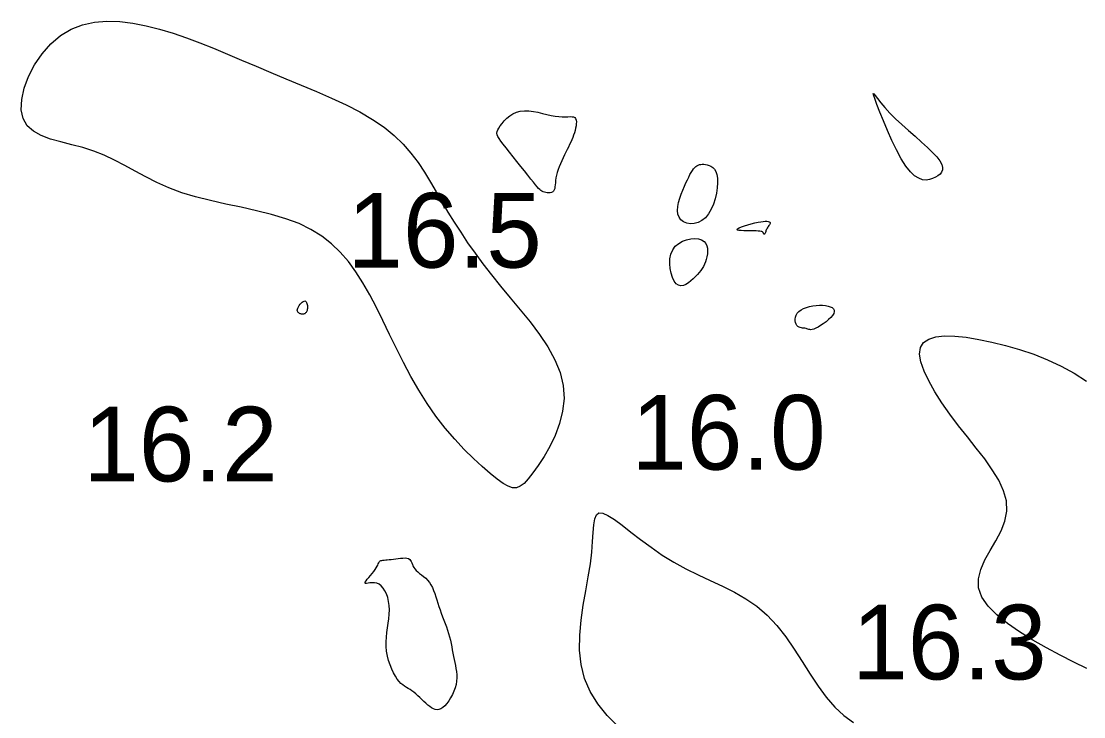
# Model space of a CAD drawing. Extents: x 3040093 to 3056816, y 408076 to 509144.
# Drawn here: x 3045442.3 to 3045513.5, y 434324.5 to 434371 of the extents above; entities that cross this region are included whole.
import ezdxf

# ---------------------------------------------------------------- set-up
doc = ezdxf.new("R2010")
doc.units = 0
doc.layers.add('V-CHAN-CONT-EL17', color=7, linetype='Continuous')
doc.layers.add('V-TOPO-SOUN-0610', color=7, linetype='Continuous')

msp = doc.modelspace()

# ---------------------------------------------------------------- linework, layer by layer
at = {"layer": 'V-CHAN-CONT-EL17'}
for points in [[(3045468.936, 434346.351), (3045468.412, 434347.27), (3045467.918, 434348.208), (3045467.446, 434349.153), (3045466.991, 434350.091), (3045466.546, 434351.012), (3045466.105, 434351.902), (3045465.661, 434352.75), (3045465.208, 434353.545), (3045464.735, 434354.283), (3045464.233, 434354.966), (3045463.691, 434355.591), (3045463.1, 434356.159), (3045462.449, 434356.667), (3045461.728, 434357.117), (3045460.928, 434357.506), (3045460.042, 434357.836), (3045459.087, 434358.119), (3045458.084, 434358.368), (3045457.054, 434358.597), (3045456.017, 434358.818), (3045454.994, 434359.046), (3045454.006, 434359.293), (3045453.074, 434359.574), (3045452.214, 434359.897), (3045451.416, 434360.254), (3045450.668, 434360.631), (3045449.956, 434361.016), (3045449.265, 434361.394), (3045448.583, 434361.753), (3045447.895, 434362.081), (3045447.187, 434362.362), (3045446.452, 434362.591), (3045445.709, 434362.785), (3045444.983, 434362.968), (3045444.296, 434363.162), (3045443.676, 434363.392), (3045443.145, 434363.682), (3045442.729, 434364.053), (3045442.453, 434364.531), (3045442.334, 434365.129), (3045442.366, 434365.822), (3045442.535, 434366.577), (3045442.828, 434367.36), (3045443.231, 434368.137), (3045443.73, 434368.874), (3045444.312, 434369.537), (3045444.964, 434370.092), (3045445.673, 434370.513), (3045446.43, 434370.804), (3045447.23, 434370.978), (3045448.063, 434371.048), (3045448.923, 434371.025), (3045449.803, 434370.922), (3045450.696, 434370.751), (3045451.594, 434370.525), (3045452.492, 434370.255), (3045453.391, 434369.947), (3045454.296, 434369.607), (3045455.211, 434369.241), (3045456.138, 434368.854), (3045457.082, 434368.451), (3045458.047, 434368.037), (3045459.036, 434367.619), (3045460.05, 434367.2), (3045461.076, 434366.778), (3045462.099, 434366.349), (3045463.104, 434365.908), (3045464.073, 434365.452), (3045464.993, 434364.978), (3045465.846, 434364.479), (3045466.618, 434363.954), (3045467.298, 434363.399), (3045467.894, 434362.817), (3045468.421, 434362.211), (3045468.892, 434361.585), (3045469.321, 434360.942), (3045469.722, 434360.287), (3045470.11, 434359.623), (3045470.496, 434358.954), (3045470.895, 434358.282), (3045471.311, 434357.606), (3045471.75, 434356.923), (3045472.213, 434356.23), (3045472.707, 434355.526), (3045473.235, 434354.807), (3045473.801, 434354.07), (3045474.409, 434353.314), (3045475.058, 434352.536), (3045475.727, 434351.738), (3045476.387, 434350.923), (3045477.012, 434350.093), (3045477.574, 434349.25), (3045478.047, 434348.398), (3045478.402, 434347.538), (3045478.614, 434346.674), (3045478.663, 434345.809), (3045478.569, 434344.956), (3045478.361, 434344.127), (3045478.065, 434343.336), (3045477.711, 434342.597), (3045477.327, 434341.923), (3045476.94, 434341.327), (3045476.58, 434340.822), (3045476.266, 434340.421), (3045475.99, 434340.123), (3045475.735, 434339.926), (3045475.484, 434339.83), (3045475.221, 434339.831), (3045474.93, 434339.929), (3045474.594, 434340.122), (3045474.195, 434340.408), (3045473.724, 434340.783), (3045473.189, 434341.244), (3045472.606, 434341.784), (3045471.99, 434342.397), (3045471.356, 434343.078), (3045470.719, 434343.819), (3045470.094, 434344.616), (3045469.495, 434345.462)], [(3045499.382, 434366.113), (3045499.36, 434366.217), (3045499.397, 434366.2), (3045499.495, 434366.08), (3045499.651, 434365.873), (3045499.865, 434365.596), (3045500.137, 434365.268), (3045500.466, 434364.906), (3045500.849, 434364.524), (3045501.27, 434364.133), (3045501.713, 434363.738), (3045502.158, 434363.347), (3045502.59, 434362.967), (3045502.989, 434362.606), (3045503.338, 434362.269), (3045503.62, 434361.965), (3045503.821, 434361.698), (3045503.945, 434361.467), (3045504, 434361.267), (3045503.994, 434361.095), (3045503.935, 434360.946), (3045503.832, 434360.818), (3045503.693, 434360.705), (3045503.526, 434360.605), (3045503.338, 434360.516), (3045503.131, 434360.45), (3045502.906, 434360.422), (3045502.664, 434360.445), (3045502.405, 434360.536), (3045502.132, 434360.707), (3045501.844, 434360.975), (3045501.542, 434361.353), (3045501.23, 434361.848), (3045500.914, 434362.433), (3045500.604, 434363.073), (3045500.309, 434363.734), (3045500.038, 434364.378), (3045499.801, 434364.973), (3045499.607, 434365.482), (3045499.464, 434365.871)], [(3045476.244, 434360.739), (3045476.014, 434361.028), (3045475.766, 434361.338), (3045475.509, 434361.66), (3045475.254, 434361.981), (3045475.009, 434362.289), (3045474.785, 434362.573), (3045474.592, 434362.822), (3045474.435, 434363.027), (3045474.317, 434363.194), (3045474.235, 434363.331), (3045474.187, 434363.449), (3045474.172, 434363.555), (3045474.187, 434363.66), (3045474.231, 434363.771), (3045474.302, 434363.898), (3045474.399, 434364.048), (3045474.52, 434364.213), (3045474.666, 434364.385), (3045474.835, 434364.555), (3045475.027, 434364.714), (3045475.241, 434364.853), (3045475.478, 434364.963), (3045475.736, 434365.035), (3045476.014, 434365.063), (3045476.307, 434365.053), (3045476.61, 434365.013), (3045476.918, 434364.954), (3045477.224, 434364.883), (3045477.523, 434364.81), (3045477.81, 434364.744), (3045478.078, 434364.694), (3045478.324, 434364.665), (3045478.547, 434364.655), (3045478.746, 434364.656), (3045478.921, 434364.662), (3045479.072, 434364.666), (3045479.2, 434364.661), (3045479.303, 434364.641), (3045479.383, 434364.599), (3045479.439, 434364.53), (3045479.474, 434364.436), (3045479.489, 434364.321), (3045479.487, 434364.19), (3045479.471, 434364.046), (3045479.442, 434363.893), (3045479.402, 434363.735), (3045479.355, 434363.577), (3045479.302, 434363.42), (3045479.243, 434363.265), (3045479.179, 434363.11), (3045479.11, 434362.954), (3045479.037, 434362.795), (3045478.958, 434362.632), (3045478.875, 434362.462), (3045478.788, 434362.286), (3045478.697, 434362.101), (3045478.604, 434361.909), (3045478.512, 434361.712), (3045478.424, 434361.514), (3045478.341, 434361.315), (3045478.268, 434361.118), (3045478.205, 434360.925), (3045478.156, 434360.739), (3045478.122, 434360.562), (3045478.1, 434360.394), (3045478.085, 434360.238), (3045478.073, 434360.095), (3045478.059, 434359.966), (3045478.04, 434359.854), (3045478.011, 434359.759), (3045477.966, 434359.682), (3045477.904, 434359.626), (3045477.827, 434359.588), (3045477.739, 434359.567), (3045477.643, 434359.559), (3045477.543, 434359.565), (3045477.443, 434359.581), (3045477.347, 434359.605), (3045477.259, 434359.636), (3045477.181, 434359.672), (3045477.108, 434359.718), (3045477.035, 434359.779), (3045476.955, 434359.86), (3045476.862, 434359.966), (3045476.751, 434360.102), (3045476.614, 434360.273), (3045476.446, 434360.485)], [(3045486.286, 434358.144), (3045486.262, 434358.383), (3045486.281, 434358.644), (3045486.334, 434358.918), (3045486.413, 434359.199), (3045486.51, 434359.478), (3045486.616, 434359.749), (3045486.723, 434360.002), (3045486.825, 434360.233), (3045486.92, 434360.44), (3045487.01, 434360.625), (3045487.095, 434360.789), (3045487.177, 434360.932), (3045487.256, 434361.056), (3045487.333, 434361.162), (3045487.409, 434361.251), (3045487.485, 434361.324), (3045487.562, 434361.381), (3045487.642, 434361.424), (3045487.726, 434361.454), (3045487.814, 434361.472), (3045487.91, 434361.478), (3045488.013, 434361.473), (3045488.125, 434361.459), (3045488.246, 434361.436), (3045488.373, 434361.398), (3045488.499, 434361.339), (3045488.619, 434361.255), (3045488.728, 434361.139), (3045488.821, 434360.985), (3045488.891, 434360.788), (3045488.933, 434360.542), (3045488.944, 434360.245), (3045488.922, 434359.907), (3045488.867, 434359.545), (3045488.782, 434359.174), (3045488.665, 434358.809), (3045488.517, 434358.465), (3045488.339, 434358.158), (3045488.132, 434357.903), (3045487.897, 434357.712), (3045487.643, 434357.583), (3045487.383, 434357.515), (3045487.126, 434357.502), (3045486.885, 434357.542), (3045486.669, 434357.63), (3045486.491, 434357.762), (3045486.36, 434357.935)], [(3045491.334, 434357.015), (3045491.129, 434357.017), (3045490.916, 434357.019), (3045490.709, 434357.024), (3045490.522, 434357.034), (3045490.371, 434357.051), (3045490.27, 434357.077), (3045490.235, 434357.114), (3045490.275, 434357.164), (3045490.383, 434357.223), (3045490.542, 434357.289), (3045490.741, 434357.358), (3045490.965, 434357.427), (3045491.201, 434357.492), (3045491.434, 434357.55), (3045491.651, 434357.597), (3045491.84, 434357.631), (3045492.001, 434357.653), (3045492.136, 434357.663), (3045492.245, 434357.662), (3045492.33, 434357.653), (3045492.393, 434357.635), (3045492.436, 434357.611), (3045492.459, 434357.581), (3045492.466, 434357.546), (3045492.458, 434357.508), (3045492.438, 434357.465), (3045492.41, 434357.419), (3045492.375, 434357.369), (3045492.337, 434357.317), (3045492.299, 434357.262), (3045492.263, 434357.204), (3045492.232, 434357.144), (3045492.205, 434357.084), (3045492.182, 434357.025), (3045492.162, 434356.969), (3045492.145, 434356.917), (3045492.13, 434356.873), (3045492.116, 434356.837), (3045492.102, 434356.811), (3045492.088, 434356.796), (3045492.075, 434356.792), (3045492.061, 434356.796), (3045492.048, 434356.807), (3045492.035, 434356.823), (3045492.022, 434356.844), (3045492.01, 434356.866), (3045491.999, 434356.89), (3045491.987, 434356.912), (3045491.972, 434356.933), (3045491.947, 434356.952), (3045491.909, 434356.969), (3045491.851, 434356.984), (3045491.769, 434356.996), (3045491.659, 434357.006), (3045491.514, 434357.012)], [(3045486.038, 434353.658), (3045485.919, 434353.895), (3045485.825, 434354.18), (3045485.762, 434354.495), (3045485.736, 434354.825), (3045485.752, 434355.155), (3045485.817, 434355.469), (3045485.937, 434355.75), (3045486.114, 434355.987), (3045486.338, 434356.178), (3045486.594, 434356.323), (3045486.869, 434356.424), (3045487.148, 434356.483), (3045487.419, 434356.5), (3045487.665, 434356.476), (3045487.875, 434356.414), (3045488.036, 434356.314), (3045488.152, 434356.183), (3045488.227, 434356.027), (3045488.267, 434355.853), (3045488.278, 434355.668), (3045488.264, 434355.478), (3045488.232, 434355.29), (3045488.186, 434355.11), (3045488.132, 434354.943), (3045488.069, 434354.789), (3045487.996, 434354.644), (3045487.914, 434354.505), (3045487.82, 434354.37), (3045487.714, 434354.236), (3045487.595, 434354.1), (3045487.462, 434353.96), (3045487.316, 434353.814), (3045487.159, 434353.672), (3045486.994, 434353.543), (3045486.825, 434353.439), (3045486.656, 434353.37), (3045486.489, 434353.347), (3045486.328, 434353.381), (3045486.176, 434353.483)], [(3045461.005, 434351.479), (3045460.957, 434351.499), (3045460.911, 434351.525), (3045460.871, 434351.558), (3045460.839, 434351.599), (3045460.818, 434351.648), (3045460.81, 434351.706), (3045460.818, 434351.774), (3045460.844, 434351.852), (3045460.884, 434351.937), (3045460.937, 434352.023), (3045460.998, 434352.107), (3045461.064, 434352.183), (3045461.133, 434352.248), (3045461.199, 434352.297), (3045461.262, 434352.325), (3045461.316, 434352.329), (3045461.363, 434352.312), (3045461.403, 434352.276), (3045461.435, 434352.226), (3045461.46, 434352.166), (3045461.479, 434352.097), (3045461.491, 434352.025), (3045461.497, 434351.953), (3045461.498, 434351.884), (3045461.492, 434351.818), (3045461.482, 434351.757), (3045461.467, 434351.7), (3045461.449, 434351.648), (3045461.426, 434351.601), (3045461.4, 434351.561), (3045461.371, 434351.526), (3045461.34, 434351.498), (3045461.306, 434351.477), (3045461.27, 434351.461), (3045461.231, 434351.452), (3045461.19, 434351.447), (3045461.147, 434351.448), (3045461.102, 434351.454), (3045461.055, 434351.464)], [(3045494.204, 434350.772), (3045494.164, 434350.877), (3045494.14, 434350.995), (3045494.137, 434351.122), (3045494.156, 434351.254), (3045494.202, 434351.386), (3045494.277, 434351.512), (3045494.385, 434351.628), (3045494.527, 434351.731), (3045494.698, 434351.82), (3045494.892, 434351.893), (3045495.102, 434351.952), (3045495.322, 434351.996), (3045495.544, 434352.025), (3045495.764, 434352.039), (3045495.973, 434352.039), (3045496.167, 434352.022), (3045496.339, 434351.991), (3045496.488, 434351.945), (3045496.607, 434351.885), (3045496.694, 434351.809), (3045496.745, 434351.719), (3045496.755, 434351.615), (3045496.72, 434351.497), (3045496.639, 434351.365), (3045496.519, 434351.225), (3045496.369, 434351.082), (3045496.2, 434350.94), (3045496.019, 434350.806), (3045495.838, 434350.684), (3045495.665, 434350.581), (3045495.51, 434350.5), (3045495.38, 434350.447), (3045495.273, 434350.418), (3045495.184, 434350.408), (3045495.11, 434350.413), (3045495.045, 434350.429), (3045494.985, 434350.45), (3045494.926, 434350.472), (3045494.862, 434350.49), (3045494.791, 434350.502), (3045494.715, 434350.51), (3045494.634, 434350.517), (3045494.552, 434350.528), (3045494.471, 434350.547), (3045494.394, 434350.576), (3045494.322, 434350.622), (3045494.257, 434350.686)], [(3045469.416, 434325.403), (3045469.283, 434325.525), (3045469.149, 434325.652), (3045469.014, 434325.781), (3045468.879, 434325.908), (3045468.744, 434326.029), (3045468.612, 434326.141), (3045468.482, 434326.24), (3045468.355, 434326.325), (3045468.231, 434326.4), (3045468.11, 434326.472), (3045467.989, 434326.548), (3045467.869, 434326.634), (3045467.748, 434326.738), (3045467.626, 434326.865), (3045467.502, 434327.022), (3045467.376, 434327.215), (3045467.25, 434327.441), (3045467.13, 434327.693), (3045467.02, 434327.969), (3045466.923, 434328.262), (3045466.844, 434328.569), (3045466.787, 434328.883), (3045466.756, 434329.202), (3045466.753, 434329.519), (3045466.773, 434329.835), (3045466.809, 434330.148), (3045466.854, 434330.458), (3045466.901, 434330.765), (3045466.942, 434331.067), (3045466.971, 434331.365), (3045466.98, 434331.658), (3045466.964, 434331.944), (3045466.924, 434332.219), (3045466.861, 434332.479), (3045466.778, 434332.719), (3045466.676, 434332.932), (3045466.558, 434333.116), (3045466.425, 434333.263), (3045466.28, 434333.371), (3045466.126, 434333.435), (3045465.969, 434333.464), (3045465.816, 434333.467), (3045465.673, 434333.455), (3045465.548, 434333.437), (3045465.448, 434333.424), (3045465.38, 434333.425), (3045465.35, 434333.45), (3045465.364, 434333.507), (3045465.415, 434333.593), (3045465.495, 434333.7), (3045465.595, 434333.824), (3045465.707, 434333.957), (3045465.821, 434334.095), (3045465.931, 434334.23), (3045466.026, 434334.357), (3045466.101, 434334.471), (3045466.158, 434334.572), (3045466.201, 434334.659), (3045466.234, 434334.734), (3045466.262, 434334.798), (3045466.289, 434334.851), (3045466.319, 434334.894), (3045466.357, 434334.927), (3045466.406, 434334.952), (3045466.468, 434334.97), (3045466.541, 434334.983), (3045466.627, 434334.993), (3045466.726, 434335.001), (3045466.837, 434335.01), (3045466.961, 434335.021), (3045467.099, 434335.035), (3045467.249, 434335.055), (3045467.407, 434335.077), (3045467.569, 434335.099), (3045467.729, 434335.117), (3045467.882, 434335.127), (3045468.024, 434335.128), (3045468.15, 434335.115), (3045468.254, 434335.085), (3045468.333, 434335.036), (3045468.392, 434334.97), (3045468.437, 434334.89), (3045468.474, 434334.8), (3045468.511, 434334.702), (3045468.551, 434334.599), (3045468.604, 434334.495), (3045468.673, 434334.392), (3045468.765, 434334.293), (3045468.875, 434334.196), (3045468.999, 434334.097), (3045469.132, 434333.995), (3045469.269, 434333.885), (3045469.405, 434333.767), (3045469.535, 434333.636), (3045469.655, 434333.489), (3045469.759, 434333.326), (3045469.851, 434333.147), (3045469.933, 434332.955), (3045470.007, 434332.751), (3045470.077, 434332.539), (3045470.145, 434332.32), (3045470.214, 434332.097), (3045470.287, 434331.873), (3045470.366, 434331.649), (3045470.45, 434331.425), (3045470.537, 434331.201), (3045470.624, 434330.977), (3045470.71, 434330.754), (3045470.793, 434330.531), (3045470.87, 434330.307), (3045470.94, 434330.084), (3045471.001, 434329.86), (3045471.055, 434329.637), (3045471.103, 434329.414), (3045471.146, 434329.193), (3045471.186, 434328.974), (3045471.225, 434328.758), (3045471.264, 434328.544), (3045471.305, 434328.334), (3045471.348, 434328.129), (3045471.391, 434327.925), (3045471.43, 434327.723), (3045471.462, 434327.521), (3045471.482, 434327.316), (3045471.487, 434327.107), (3045471.473, 434326.893), (3045471.437, 434326.673), (3045471.376, 434326.445), (3045471.292, 434326.214), (3045471.191, 434325.987), (3045471.075, 434325.77), (3045470.948, 434325.568), (3045470.815, 434325.387), (3045470.679, 434325.234), (3045470.544, 434325.115), (3045470.413, 434325.034), (3045470.286, 434324.989), (3045470.162, 434324.977), (3045470.039, 434324.994), (3045469.918, 434325.037), (3045469.795, 434325.103), (3045469.672, 434325.188), (3045469.545, 434325.289)]]:
    msp.add_lwpolyline(points, close=True, dxfattribs=at)
for points in [[(3045513.647, 434327.738), (3045512.781, 434328.167), (3045511.881, 434328.629), (3045510.958, 434329.12), (3045510.041, 434329.637), (3045509.162, 434330.177), (3045508.35, 434330.737), (3045507.639, 434331.315), (3045507.058, 434331.907), (3045506.639, 434332.511), (3045506.413, 434333.123), (3045506.399, 434333.742), (3045506.558, 434334.367), (3045506.84, 434334.998), (3045507.194, 434335.637), (3045507.57, 434336.282), (3045507.915, 434336.935), (3045508.18, 434337.597), (3045508.313, 434338.266), (3045508.277, 434338.944), (3045508.084, 434339.631), (3045507.759, 434340.329), (3045507.33, 434341.036), (3045506.82, 434341.755), (3045506.256, 434342.485), (3045505.663, 434343.227), (3045505.068, 434343.982), (3045504.493, 434344.748), (3045503.958, 434345.512), (3045503.48, 434346.259), (3045503.075, 434346.974), (3045502.759, 434347.642), (3045502.55, 434348.248), (3045502.465, 434348.777), (3045502.521, 434349.214), (3045502.728, 434349.547), (3045503.078, 434349.781), (3045503.554, 434349.925), (3045504.142, 434349.987), (3045504.826, 434349.974), (3045505.591, 434349.896), (3045506.422, 434349.761), (3045507.303, 434349.577), (3045508.22, 434349.35), (3045509.157, 434349.08), (3045510.1, 434348.762), (3045511.034, 434348.393), (3045511.944, 434347.971), (3045512.815, 434347.492), (3045513.633, 434346.952)], [(3045482.276, 434323.869), (3045481.561, 434324.596), (3045480.933, 434325.368), (3045480.416, 434326.188), (3045480.035, 434327.063), (3045479.805, 434327.993), (3045479.709, 434328.964), (3045479.72, 434329.961), (3045479.81, 434330.966), (3045479.952, 434331.962), (3045480.121, 434332.933), (3045480.288, 434333.861), (3045480.427, 434334.729), (3045480.519, 434335.523), (3045480.575, 434336.231), (3045480.615, 434336.843), (3045480.659, 434337.35), (3045480.724, 434337.743), (3045480.832, 434338.012), (3045481.001, 434338.147), (3045481.251, 434338.138), (3045481.597, 434337.983), (3045482.033, 434337.702), (3045482.55, 434337.321), (3045483.139, 434336.866), (3045483.789, 434336.364), (3045484.492, 434335.842), (3045485.238, 434335.325), (3045486.017, 434334.84), (3045486.82, 434334.406), (3045487.636, 434334.01), (3045488.457, 434333.633), (3045489.271, 434333.252), (3045490.069, 434332.849), (3045490.841, 434332.403), (3045491.578, 434331.894), (3045492.268, 434331.301), (3045492.907, 434330.612), (3045493.501, 434329.846), (3045494.063, 434329.029), (3045494.603, 434328.191), (3045495.135, 434327.356), (3045495.668, 434326.552), (3045496.215, 434325.808), (3045496.788, 434325.148), (3045497.394, 434324.592), (3045498.031, 434324.118)]]:
    msp.add_lwpolyline(points, dxfattribs=at)

# ---------------------------------------------------------------- texts
at = {"layer": 'V-TOPO-SOUN-0610'}
for s, p in [('16.5 ', (3045464.163, 434354.56)), ('16.0 ', (3045483.163, 434341.04)), ('16.2 ', (3045446.483, 434340.25)), ('16.3 ', (3045497.953, 434327))]:
    msp.add_text(s, height=5, dxfattribs=at).set_placement(p)

doc.saveas('drawing.dxf')
